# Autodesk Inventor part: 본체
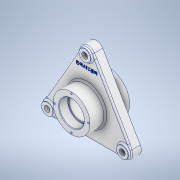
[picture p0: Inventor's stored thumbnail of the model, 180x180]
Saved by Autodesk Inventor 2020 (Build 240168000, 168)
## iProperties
Created: 2023-04
Part Number: 본체
Material: 알루미늄 6061
Document SubType Name: Modeling
Designer: 101-13
Density: 2.7 g/cm^3
Appearance: 알루미늄 - 평지
Mass: 1049.94 g
Surface Area: 595.9 cm^2
Volume: 388.865 cm^3
Author: 101-13
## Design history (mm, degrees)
sketch "스케치1" dims "d0" = 164
  geometry: L1 (0, 89.768)-(0, -89.768); L2 (-111.881, 0)-(111.881, 0); L3 (55.941, -96.892)-(-55.941, 96.892); L4 (55.941, 96.892)-(-55.941, -96.892); L5 (-83.138, -34)-(-12.124, 89); L6 (13.636, 86.382)-(83.138, -34); L7 (-71.014, -55)-(71.014, -55); L8 (13.636, 86.382)-(12.124, 89); C1 r 11 at (0, 82); C2 r 11 at (-71.014, -41); C3 r 11 at (71.014, -41); A1 r 14 centre (71.014, -41) between (71.014, -55) and (83.138, -34); A2 r 14 centre (0, 82) between (12.124, 89) and (-12.124, 89); A3 r 14 centre (-71.014, -41) between (-83.138, -34) and (-71.014, -55); 6 further points
  constraints: 16 end point, 6 centre point, 6 point on circle, 3 coincident, 2 midpoint, 2 point on line, 1 horizontal, 1 tangent, 1 vertical, 1 vertical alignment, 21 other
  dimensions: "d1" = 22 diameter of C1; "d4" = 360 deg dimension on point (0, 0) L2.start (derived)
extrude "돌출1" new body sketch "스케치1" stored distance "d12" = 18; taper "d13" = 0 deg
extrude "돌출3" join sketch "스케치1" distance "d16" = 13; taper "d17" = 0 deg
sketch "스케치5"
  geometry: C1 r 35 at (0, 0); 1 further point
  constraints: 1 centre point, 1 coincident
  dimensions: "d19" = 70 diameter of C1
extrude "돌출4" join sketch "스케치5" distance "d20" = 29; taper "d21" = 0 deg
sketch "스케치6"
  geometry: C1 r 45 at (0, 0); 1 further point
  constraints: 1 centre point, 1 coincident
  dimensions: "d22" = 90 diameter of C1
extrude "돌출5" join sketch "스케치6" distance "d23" = 5; taper "d24" = 0 deg
sketch "스케치7"
  geometry: C1 r 40 at (0, 0); 1 further point
  constraints: 1 centre point, 1 coincident
  dimensions: "d25" = 80 diameter of C1
extrude "돌출6" join sketch "스케치7" distance "d26" = 18; taper "d27" = 0 deg
fillet "모깎기1" dims "d28" = 3
fillet "모깎기2" dims "d29" = 3
fillet "모깎기3" dims "d30" = 3
fillet "모깎기4" dims "d31" = 3
sketch "스케치8"
  geometry: 2 further points
hole "구멍1" sketch "스케치8" at (0, 0) diameter "d32" = 11; stored, may be unused: countersink angle "d36" = 90 deg, drill point angle "d38" = 118 deg; dims "d33" = 8, "d34" = 4, "d35" = 2, "d37" = 10
sketch "스케치9"
  geometry: 1 further point
hole "구멍2" sketch "스케치9" at (0, 0) diameter "d42" = 42; stored, may be unused: countersink angle "d46" = 82 deg, drill point angle "d48" = 118 deg; dims "d43" = 8, "d44" = 3.023, "d45" = 2, "d47" = 10
sketch "스케치10"
  geometry: 1 further point
hole "구멍3" sketch "스케치10" at (0, 0) diameter "d49" = 47; stored, may be unused: countersink angle "d53" = 82 deg, drill point angle "d55" = 0 deg; dims "d50" = 8, "d51" = 3.023, "d52" = 2, "d54" = 17
sketch "스케치11"
  geometry: 1 further point
hole "구멍4" sketch "스케치11" at (0, 0) diameter "d56" = 47; stored, may be unused: countersink angle "d60" = 82 deg, drill point angle "d62" = 0 deg; dims "d57" = 8, "d58" = 3.023, "d59" = 2, "d61" = 17
sketch "스케치12" dims "d63" = 64
  geometry: 3 further points
  constraints: 1 coincident, 1 vertical alignment, 2 other
hole "구멍5" sketch "스케치12" at (0, 32) diameter "d64" = 3.242; stored, may be unused: countersink angle "d68" = 82 deg, drill point angle "d70" = 118 deg; dims "d65" = 8, "d66" = 3.023, "d67" = 2, "d69" = 10
sketch "스케치13" dims "d74" = 64
  geometry: 3 further points
  constraints: 1 coincident, 1 vertical alignment, 2 other
hole "구멍6" sketch "스케치13" at (0, 32) diameter "d75" = 3.242; stored, may be unused: countersink angle "d79" = 82 deg, drill point angle "d81" = 118 deg; dims "d76" = 8, "d77" = 3.023, "d78" = 2, "d80" = 10
chamfer "모따기1" distance "d85" = 1; stored, may be unused: second distance "d86" = 2, angle "d87" = 45 deg
fillet "모깎기5" dims "d88" = 0.6
fillet "모깎기6" dims "d89" = 0.6
sketch "스케치14"
  geometry: 2 further points
  constraints: 1 vertical alignment, 1 other
  dimensions: "d90" = 60 distance of point (0, 60) point (0, 0)
feature "엠보싱1" sketch "스케치14" dims "d91" = 0.5, "d92" = 0
node "솔리드1"
pattern_circular "원형 패턴1" dims angle "d40" = 360 deg
pattern_circular "원형 패턴2" dims angle "d72" = 360 deg
pattern_circular "원형 패턴3" dims angle "d83" = 360 deg
feature "A9D066F2-1C7D-4E18-AEED-F7BC21143FA4" dims "d32" = 11, "d33" = 8, "d34" = 4, "d35" = 2, "d36" = 90 deg, "d37" = 10, "d38" = 118 deg
other parameters: "d6" = 3, "d7" = 3, "d8" = 3, "d9" = 3, "d10" = 3, "d11" = 3
